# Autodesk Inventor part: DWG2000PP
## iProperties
Created: 2005-01
Part Number: DWG2000PP
Document SubType Name: Modeling
Designer: Konstruktion
Manufacturer: Standard
Standards Organization: Custom
Author: Konstruktion
